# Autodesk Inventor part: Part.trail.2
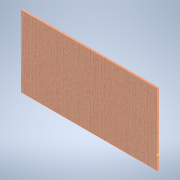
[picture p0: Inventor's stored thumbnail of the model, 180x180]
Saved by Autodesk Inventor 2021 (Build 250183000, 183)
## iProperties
Created: 2021-07
Part Number: Part.trail.2
Material: Polycarbonate, Clear
Document SubType Name: Modeling
Designer: CHIRAG
Density: 1.2 g/cm^3
Appearance: Red Oak - Natural Low Gloss
Author: CHIRAG
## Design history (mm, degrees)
sketch "Sketch1"
  geometry: 1 further point
sketch "Sketch2"
  geometry: 1 further point
sketch "Sketch3"
  geometry: L1 (0, 0)-(-501.069, 0); L2 (-501.069, 0)-(-501.069, 211.432); L3 (-501.069, 211.432)-(0, 211.432); L4 (0, 211.432)-(0, 0)
  constraints: 8 end point, 2 parallel, 1 horizontal, 1 perpendicular
extrude "Extrusion1" new body sketch "Sketch3" distance "d0" = 5; taper "d1" = 0 deg
sketch "Sketch4"
  geometry: 1 further point
sketch "Sketch11"
  geometry: L1 (501.069, 0)-(0, 0); L2 (0, 0)-(0, -51.378); L3 (0, -51.378)-(501.069, -51.378); L4 (501.069, -51.378)-(501.069, 0); 1 further point
  constraints: 8 end point, 2 parallel, 1 horizontal, 1 perpendicular
extrude "Extrusion5" join sketch "Sketch11" distance "d8" = 5; taper "d9" = 0 deg
body "Solid1"
